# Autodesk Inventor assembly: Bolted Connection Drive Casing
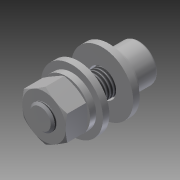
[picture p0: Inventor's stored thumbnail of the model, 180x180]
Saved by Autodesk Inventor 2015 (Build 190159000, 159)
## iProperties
Created: 2007-02
Part Number: Bolted Connection Drive Casing
Document SubType Name: Assembly
Designer: Autodesk, Inc.
Mass: 17.5979 g
Surface Area: 26.518 cm^2
Volume: 2.23891 cm^3
Density: 7.86 g/cm^3
ClientObjectVersion: 1
Author: Autodesk, Inc.
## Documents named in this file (5)
- C:\Users\Public\Documents\Autodesk\Inventor 2015\Samples\Models\Assemblies\Blower\Blower\Design Accelerator\Bolted Connection1.iam
- C:\Users\Public\Documents\Autodesk\Inventor 2015\Samples\Standard Parts\en-US\ANSI B18.22.1\ANSI B18.22.1 - 1_4 - narrow - Type A.ipt
- C:\Users\Public\Documents\Autodesk\Inventor 2015\Samples\Standard Parts\en-US\ANSI B18.21.1\ANSI B18.21.1 - 0.25.ipt
- C:\Users\Public\Documents\Autodesk\Inventor 2015\Samples\Standard Parts\en-US\ANSI B18.3(13)\ANSI B18.3 - 1_4-28 UNF - 0.75(22).ipt
- C:\Users\Public\Documents\Autodesk\Inventor 2015\Samples\Standard Parts\en-US\ANSI B18.2.2(09)\ANSI B18.2.2 - 1_4 - 28(2).ipt
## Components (6 placed, 4 different names)
1. ANSI B18.22.1 - 1/4 - narrow - Type A:1
2. ANSI B18.21.1 - 0.25:2
3. ANSI B18.3 - 1/4-28 UNF - 0.75:3
4. ANSI B18.22.1 - 1/4 - narrow - Type A:4
5. ANSI B18.21.1 - 0.25:5
6. ANSI B18.2.2 - 1/4 - 28:6
